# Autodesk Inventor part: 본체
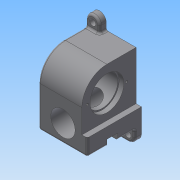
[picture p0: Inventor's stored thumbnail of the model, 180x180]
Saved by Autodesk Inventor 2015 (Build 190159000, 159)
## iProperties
Created: 2019-06
Part Number: 본체
Material: 알루미늄 6061
Document SubType Name: Modeling
Designer: mduedu
Density: 2.71 g/cm^3
Appearance: 기본값
Mass: 866.343 g
Surface Area: 554.994 cm^2
Volume: 319.684 cm^3
Author: mduedu
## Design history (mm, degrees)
sketch "스케치1"
  geometry: L1 (37, 0)-(37, -43); L2 (37, -43)-(-60, -43); L3 (-60, -43)-(-60, 37); L4 (-60, 37)-(0, 37); A1 r 37 centre (0, 0) between (37, 0) and (0, 37); 1 further point
  constraints: 8 end point, 2 point on circle, 2 tangent, 1 centre point, 1 coincident, 1 horizontal, 1 parallel, 1 perpendicular, 1 vertical
  dimensions: "d0" = 37 radius of A1; "d2" = 80 distance of L2.end L3.end; "d3" = 97 distance of L1.end L2.end
extrude "돌출1" new body sketch "스케치1" stored distance "d4" = 72; taper "d5" = 0 deg
sketch "스케치2"
  geometry: L1 (72, 25)-(64, 25); L2 (64, 25)-(64, 97); L3 (64, 97)-(72, 97); L4 (72, 97)-(72, 25); L5 (72, 97)-(0, 97) reference; L6 (72, 60)-(72, 0) reference; 1 further point
  constraints: 8 end point, 2 collinear, 2 parallel, 1 horizontal, 1 perpendicular
  dimensions: "d6" = 72 distance between parallel lines of L1 L3; "d8" = 8 distance of L1.start L1.end
extrude "돌출2" cut sketch "스케치2" stored distance "d9" = 72; taper "d10" = 0 deg
sketch "스케치3"
  geometry: L1 (-36, -60)-(-36, 37) reference; L2 (-36, 37)-(28, 37) reference; L3 (28, 37)-(28, -35) reference; L4 (28, -35)-(36, -35) reference; L5 (36, -35)-(36, -60) reference; L6 (36, -60)-(-36, -60) reference; L7 (-36, 0)-(-19, 0); L8 (-19, 0)-(-19, 17.5); L9 (-19, 17.5)-(-36, 17.5); L10 (-36, 17.5)-(-36, 0); L11 (-19, 0)-(21, 0); L12 (21, 0)-(21, 23); L13 (21, 23)-(-19, 23); L14 (-19, 23)-(-19, 0); L15 (21, 0)-(28, 0); L16 (28, 0)-(28, 25); L17 (28, 25)-(21, 25); L18 (21, 25)-(21, 0); 1 further point
  constraints: 24 end point, 6 parallel, 3 horizontal, 3 perpendicular, 2 point on line, 1 horizontal alignment
  dimensions: "d11" = 7 distance of L16.end L17.end; "d13" = 47 distance between parallel lines of L3 L8; "d14" = 50 diameter of L17 L15; "d15" = 46 diameter of L13 L11; "d16" = 35 diameter of L9 L7
revolve "회전1" sketch "스케치3" stored, may be unused: angle "d17" = 90 deg
sketch "스케치4"
  geometry: C1 r 28 at (0, 0); 1 further point
  constraints: 1 centre point, 1 coincident
  dimensions: "d18" = 56 diameter of C1
extrude "돌출3" cut sketch "스케치4" distance "d19" = 2; taper "d20" = 0 deg
fillet "모깎기1" dims "d21" = 3
sketch "스케치5"
  geometry: C1 r 18 at (36, 26); 1 further point
  constraints: 1 centre point, 1 vertical alignment
  dimensions: "d22" = 36 diameter of C1; "d23" = 34 distance of C1.centre point (36, 60)
extrude "돌출4" cut sketch "스케치5" stored distance "d24" = 2; taper "d25" = 0 deg
sketch "스케치6"
  geometry: L1 (-37, -60)-(43, -60) reference; L2 (-8, -60)-(8, -60); L3 (8, -60)-(8, -51); L4 (8, -51)-(-8, -51); L5 (-8, -51)-(-8, -60); 2 further points
  constraints: 8 end point, 2 parallel, 1 horizontal, 1 midpoint, 1 perpendicular, 1 point on line, 1 vertical alignment
  dimensions: "d26" = 16 distance between parallel lines of L3 L5; "d28" = 9 distance between parallel lines of L1 L4
extrude "돌출5" cut sketch "스케치6" stored distance "d29" = 2; taper "d30" = 0 deg
sketch "스케치7"
  geometry: L1 (-10, -60)-(10, -60); L2 (10, -60)-(10, -48.967); L3 (10, -48.967)-(-10, -48.967); L4 (-10, -48.967)-(-10, -60); L5 (36, -60)-(-36, -60) reference; 3 further points
  constraints: 8 end point, 2 parallel, 1 collinear, 1 horizontal, 1 midpoint, 1 perpendicular, 1 vertical alignment, 2 other
  dimensions: "d31" = 20 distance of L2.end L3.end
extrude "돌출6" cut sketch "스케치7" stored distance "d33" = 2; taper "d34" = 0 deg
sketch "스케치8"
  geometry: L1 (0, 25)-(8, 25) reference; L2 (8, 25)-(8, 60) reference; L3 (72, 60)-(8, 60) reference; L4 (72, 0)-(72, 60) reference; L5 (72, 0)-(0, 0) reference; L6 (0, 25)-(0, 0) reference; L7 (72, 0)-(0, 0); L8 (0, 0)-(0, -20); L9 (0, -20)-(72, -20); L10 (72, -20)-(72, 0); C1 r 18 at (36, 26) reference; 1 further point
  constraints: 8 end point, 2 parallel, 1 horizontal, 1 perpendicular, 1 point on line
  dimensions: "d35" = 20 distance of L7.end L8.end
extrude "돌출7" join sketch "스케치8" distance "d37" = 10; taper "d38" = 0 deg
sketch "스케치9"
  geometry: L1 (0, -37)-(0, 0) reference; L2 (0, 0)-(64, 0) reference; L3 (64, -37)-(64, 0) reference; L4 (44, 0)-(64, 0); L5 (64, 0)-(64, 20); L6 (64, 20)-(44, 20); L7 (44, 20)-(44, 0); 1 further point
  constraints: 9 end point, 2 perpendicular, 1 horizontal, 1 parallel
  dimensions: "d39" = 20 distance of L2.end L5.end; "d51" = 20 distance of L5.end L6.end
extrude "돌출8" join sketch "스케치9" distance "d41" = 10; taper "d42" = 0 deg
fillet "모깎기2" dims "d43" = 10
sketch "스케치10"
  geometry: L1 (-62, -20)-(-10, -20) reference; L2 (0, -10)-(0, 0) reference; L3 (-72, 0)-(0, 0) reference; L4 (-72, 0)-(-72, -10) reference; C1 r 4.5 at (-62, -10); C2 r 4.5 at (-10, -10); A1 r 10 centre (-62, -10) between (-72, -10) and (-62, -20) reference; A2 r 10 centre (-10, -10) between (-10, -20) and (0, -10) reference; 1 further point
  constraints: 2 centre point, 2 coincident, 1 equal radius
  dimensions: "d44" = 9 diameter of C1
extrude "돌출9" cut sketch "스케치10" stored distance "d45" = 10; taper "d46" = 0 deg
sketch "스케치11"
  geometry: L1 (-64, 10)-(-64, 0) reference; L2 (-44, 0)-(-64, 0) reference; L3 (-44, 0)-(-44, 10) reference; C1 r 4.5 at (-54, 10); A1 r 10 centre (-54, 10) between (-44, 10) and (-64, 10) reference; 1 further point
  constraints: 1 centre point, 1 coincident
  dimensions: "d47" = 9 diameter of C1
extrude "돌출10" cut sketch "스케치11" stored distance "d48" = 10; taper "d49" = 0 deg
fillet "모깎기4" dims "d52" = 3
fillet "모깎기5" dims "d53" = 3
fillet "모깎기6" dims "d54" = 3
fillet "모깎기7" dims "d55" = 3
sketch "스케치12" dims "d56" = 58
  geometry: 3 further points
  constraints: 2 horizontal alignment, 1 coincident, 2 other
hole "구멍1" sketch "스케치12" at (66, 35) diameter "d57" = 3.242; stored, may be unused: countersink angle "d61" = 90 deg, drill point angle "d63" = 118 deg; dims "d58" = 10, "d59" = 4, "d60" = 2, "d62" = 12
sketch "스케치13" dims "d67" = 44
  geometry: 3 further points
  constraints: 2 vertical alignment, 1 coincident, 2 other
hole "구멍2" sketch "스케치13" at (0, 22) diameter "d68" = 3.242; stored, may be unused: countersink angle "d72" = 90 deg, drill point angle "d74" = 118 deg; dims "d69" = 10, "d70" = 4, "d71" = 2, "d73" = 12
sketch "스케치14"
  geometry: 3 further points
  constraints: 2 horizontal alignment
  dimensions: "d78" = 25 distance of point (11, 8) point (36, 8); "d79" = 25 distance of point (61, 8) point (36, 8)
hole "구멍3" sketch "스케치14" at (11, 8), (61, 8) diameter "d80" = 3.242; stored, may be unused: countersink angle "d84" = 90 deg, drill point angle "d86" = 118 deg; dims "d81" = 8, "d82" = 4, "d83" = 2, "d85" = 10
node "솔리드1"
pattern_circular "원형 패턴1" dims angle "d65" = 360 deg
pattern_circular "원형 패턴2" dims angle "d76" = 360 deg
node "투영된 루프1"
node "투영된 루프2"
node "투영된 루프3"
node "절단 모서리 투영1"
